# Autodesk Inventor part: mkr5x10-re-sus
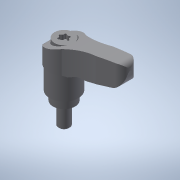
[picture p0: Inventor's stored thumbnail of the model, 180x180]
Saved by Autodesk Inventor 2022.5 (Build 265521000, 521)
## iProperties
Created: 2017-09
Part Number: mkr5x10-re-sus
Material: 一般
Document SubType Name: Modeling
Designer: imaocorp
Density: 1 g/cm^3
Appearance: 既定
Author: imaocorp
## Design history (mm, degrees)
node "mkr5x10-re-sus.x_t1"
node "mkr5x10-re-sus"
node "Base1"
